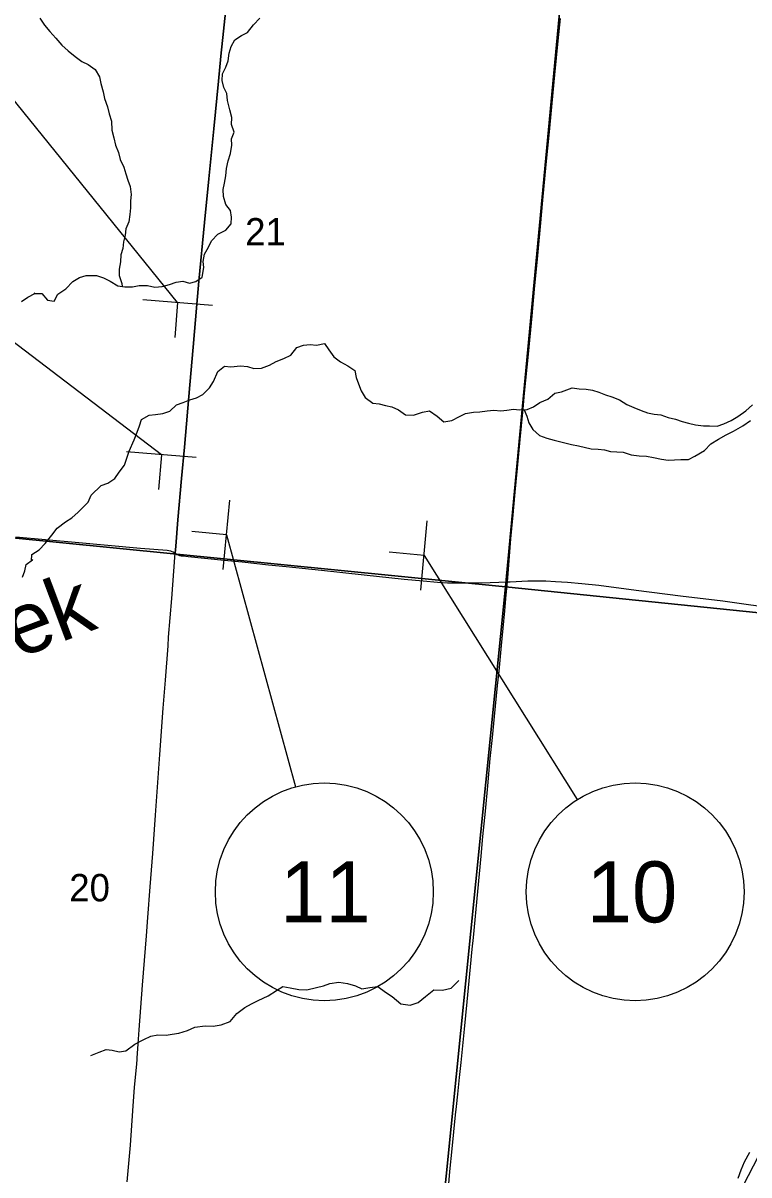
# Model space of a CAD drawing. Extents: x 0 to 1101, y 0 to 440.
# Drawn here: x 242.4 to 275.7, y 64.6 to 117.4 of the extents above; entities that cross this region are included whole.
import ezdxf

# ---------------------------------------------------------------- set-up
doc = ezdxf.new("R2010")
doc.units = 0
for name, color, linetype in [('Default', 7, 'Continuous'), ('GM_X_Minor_River', 7, 'Continuous'), ('GM_X_Minor_River_Text', 7, 'Continuous'), ('GM_X_Rail_Line', 7, 'Continuous'), ('GM_X_Section', 7, 'Continuous'), ('GM_X_Section_Text', 7, 'Continuous'), ('GM_X_State_Route', 7, 'Continuous'), ('GM_X_Township_Road', 7, 'Continuous'), ('GM_X_US_Route', 7, 'Continuous'), ('SH_Masking', 7, 'Continuous'), ('SH_Text', 7, 'Continuous'), ('SN_P_Signs', 7, 'Continuous')]:
    doc.layers.add(name, color=color, linetype=linetype)

msp = doc.modelspace()

# ---------------------------------------------------------------- linework, layer by layer
at = {"layer": 'Default'}
for points in [[(252.063, 121.444), (251.599, 117.072), (251.481, 115.922), (251.37, 114.772), (251.149, 112.584), (250.924, 110.283), (250.733, 108.279), (250.473, 105.589), (250.377, 104.531), (250.205, 102.562), (250.054, 100.835), (249.804, 97.976), (249.672, 96.528), (249.501, 94.634), (249.403, 93.416), (249.383, 93.096)], [(249.383, 93.096), (249.458, 93.046), (249.516, 93.02), (249.579, 93), (249.655, 92.986), (249.74, 92.977), (249.975, 92.954), (251.628, 92.788), (252.462, 92.697), (253.667, 92.571), (254.483, 92.487), (256.095, 92.315), (258.06, 92.112), (259.895, 91.912), (260.767, 91.826), (261.417, 91.766), (261.884, 91.743), (262.406, 91.734), (263.152, 91.736), (263.842, 91.753), (264.635, 91.788)], [(264.635, 91.788), (264.755, 91.793), (265.574, 91.828), (266.002, 91.833), (266.392, 91.827), (266.839, 91.809), (267.396, 91.772), (268.045, 91.713), (268.822, 91.626), (270.542, 91.411), (272.576, 91.151), (274.517, 90.907), (275.699, 90.747), (277.398, 90.516), (278.71, 90.338), (279.56, 90.23), (280.101, 90.164)]]:
    msp.add_lwpolyline(points, dxfattribs=at)
at = {"layer": 'GM_X_Minor_River'}
for points in [[(242.93, 105.021), (243.255, 105.021), (243.526, 104.722), (243.823, 104.673), (243.986, 104.992), (244.365, 105.24), (244.676, 105.568), (244.986, 105.76), (245.295, 105.848), (245.775, 105.855), (246.094, 105.749), (246.401, 105.587), (246.742, 105.378), (247.073, 105.329), (247.415, 105.326), (247.724, 105.391), (248.113, 105.388), (248.443, 105.316), (248.786, 105.347), (249.118, 105.435), (249.427, 105.547), (249.725, 105.59), (250.044, 105.495), (250.33, 105.573), (250.617, 105.776), (250.69, 106.209), (250.658, 106.496), (250.73, 106.826), (250.904, 107.156), (251.055, 107.441), (251.343, 107.746), (251.699, 107.926), (251.953, 108.221), (251.967, 108.529), (251.924, 108.827), (251.709, 109.115), (251.599, 109.481), (251.59, 109.801), (251.65, 110.086), (251.71, 110.429), (251.736, 110.76), (251.819, 111.113), (251.913, 111.444), (251.974, 111.832), (251.965, 112.118), (252.082, 112.436), (251.971, 112.78), (251.974, 113.1), (251.885, 113.455), (251.786, 113.879), (251.744, 114.199), (251.62, 114.486), (251.543, 114.795), (251.558, 115.103), (251.709, 115.41), (251.814, 115.706), (251.852, 116.049), (251.946, 116.368), (252.12, 116.675), (252.419, 116.866), (252.705, 117), (252.971, 117.363), (253.26, 117.658)], [(243.17, 117.661), (243.377, 117.339), (243.625, 117.051), (243.908, 116.751), (244.179, 116.417), (244.474, 116.163), (244.791, 115.909), (245.098, 115.678), (245.382, 115.538), (245.7, 115.307), (245.902, 114.962), (245.968, 114.664), (246.067, 114.275), (246.133, 113.977), (246.278, 113.599), (246.356, 113.278), (246.455, 112.935), (246.474, 112.523), (246.563, 112.168), (246.639, 111.825), (246.774, 111.492), (246.851, 111.171), (247.019, 110.815), (247.108, 110.517), (247.208, 110.219), (247.319, 109.933), (247.362, 109.567), (247.336, 109.27), (247.322, 108.95), (247.296, 108.653), (247.259, 108.31), (247.108, 107.992), (247.082, 107.695), (247, 107.387), (246.974, 107.09), (246.891, 106.794), (246.866, 106.474), (246.806, 106.143), (246.814, 105.846), (246.925, 105.479), (246.953, 105.347)], [(242.327, 104.651), (242.618, 104.859), (242.93, 105.021), (242.908, 105.045)], [(242.777, 92.752), (242.805, 93.043), (243.139, 93.258), (243.404, 93.552), (243.716, 93.927), (243.958, 94.256), (244.338, 94.539), (244.637, 94.73), (244.924, 94.979), (245.385, 95.444), (245.525, 95.762), (245.975, 96.204), (246.295, 96.316), (246.606, 96.53), (246.802, 96.814), (247.057, 97.143), (247.268, 97.782), (247.501, 98.305), (247.63, 98.659), (247.747, 98.943), (247.829, 99.24), (248.185, 99.431), (248.471, 99.462), (248.814, 99.517), (249.135, 99.628), (249.434, 99.911), (249.744, 100.022), (250.053, 100.145), (250.362, 100.234), (250.649, 100.391), (250.96, 100.686), (251.146, 100.981), (251.333, 101.437), (251.643, 101.685), (251.94, 101.66), (252.386, 101.701), (252.694, 101.664), (252.99, 101.581), (253.344, 101.601), (253.711, 101.735), (254.021, 101.903), (254.365, 102.037), (254.686, 102.194), (254.963, 102.546), (255.273, 102.657), (255.581, 102.677), (255.867, 102.652), (256.233, 102.728), (256.436, 102.429), (256.661, 102.119), (256.968, 101.887), (257.309, 101.701), (257.626, 101.481), (257.692, 101.171), (257.792, 100.873), (257.915, 100.552), (258.107, 100.253), (258.447, 99.987), (258.744, 99.95), (259.029, 99.878), (259.325, 99.819), (259.632, 99.678), (259.95, 99.447), (260.315, 99.432), (260.728, 99.577), (261.06, 99.642), (261.411, 99.399), (261.717, 99.133), (262.084, 99.198), (262.428, 99.378), (262.715, 99.512), (263.069, 99.578), (263.366, 99.586), (263.709, 99.629), (264.007, 99.66), (264.326, 99.634), (264.612, 99.666), (264.909, 99.709), (265.195, 99.683), (265.537, 99.692), (265.836, 99.815), (266.123, 100.018), (266.49, 100.174), (266.812, 100.446), (267.11, 100.511), (267.602, 100.69), (267.922, 100.641), (268.241, 100.626), (268.538, 100.578), (268.823, 100.495), (269.142, 100.378), (269.426, 100.284), (269.779, 100.143), (270.108, 99.934), (270.438, 99.783), (270.768, 99.654), (271.064, 99.548), (271.372, 99.488), (271.68, 99.451), (272.011, 99.333), (272.352, 99.25)], [(265.408, 99.689), (265.523, 99.395), (265.623, 99.085), (265.792, 98.775), (266.098, 98.497), (266.44, 98.38), (266.781, 98.285), (267.214, 98.178), (267.579, 98.095), (267.898, 98.023), (268.48, 97.892), (268.799, 97.877), (269.085, 97.852), (269.37, 97.769), (269.655, 97.755), (269.952, 97.741), (270.316, 97.623), (270.681, 97.574), (271.012, 97.559), (271.332, 97.488), (271.708, 97.416), (272.016, 97.367), (272.587, 97.396), (272.941, 97.404), (273.24, 97.561), (273.688, 97.82), (273.976, 98.114), (274.32, 98.328), (274.676, 98.542), (275.009, 98.699), (275.434, 98.947), (275.79, 99.195)], [(272.352, 99.25), (272.649, 99.144), (272.945, 99.073), (273.275, 98.99), (273.629, 98.941), (273.915, 98.95), (274.257, 98.935), (274.567, 99.046), (274.899, 99.192), (275.209, 99.383), (275.577, 99.631), (275.888, 99.914)], [(242.368, 91.995), (242.479, 92.289), (242.533, 92.584), (242.835, 92.792), (242.847, 92.826)], [(245.51, 70.039), (245.888, 70.193), (246.208, 70.314), (246.493, 70.287), (246.811, 70.215), (247.119, 70.256), (247.522, 70.558), (247.935, 70.78), (248.267, 70.935), (248.587, 70.988), (248.963, 70.983), (249.248, 71.025), (249.545, 71.066), (249.945, 71.186), (250.289, 71.341), (250.757, 71.403), (251.121, 71.387), (251.487, 71.45), (251.899, 71.604), (252.212, 71.964), (252.58, 72.244), (252.89, 72.411), (253.188, 72.567), (253.647, 72.788), (254.026, 73.022), (254.325, 73.212), (254.666, 73.15), (255.063, 73.065), (255.428, 73.06), (255.862, 73.168), (256.194, 73.244), (256.48, 73.342), (256.891, 73.405), (257.289, 73.354), (257.651, 73.235), (257.946, 73.106), (258.322, 73.158), (258.687, 73.21), (259.037, 72.954), (259.342, 72.756), (259.747, 72.42), (260.167, 72.346), (260.534, 72.478), (260.879, 72.758), (261.248, 73.05), (261.646, 73.044), (262.046, 73.13), (262.404, 73.478)], [(275.225, 64.404), (275.368, 64.801), (275.521, 65.163), (275.755, 65.604)]]:
    msp.add_lwpolyline(points, dxfattribs=at)
at = {"layer": 'GM_X_Rail_Line'}
msp.add_lwpolyline([(255.409, 27.207), (256.335, 28.435), (257.348, 30.06), (259.79, 33.772), (261.122, 36.152), (262.358, 38.564), (264.229, 42.213), (271.458, 56.334), (279.687, 72.261), (282.678, 78.347), (284.19, 81.266), (285.604, 83.513), (287.178, 85.826), (288.594, 87.771), (290.087, 89.842), (296.767, 97.839), (304.262, 106.782), (318.318, 123.252), (336.126, 144.564), (338.926, 147.955), (340.183, 149.461), (341.32, 151.069), (352.19, 166.043), (354.798, 169.6)], dxfattribs=at)
at = {"layer": 'GM_X_Section'}
for points in [[(267.417, 122.144), (264.55, 91.562), (233.896, 94.609), (236.891, 124.822)], [(267.417, 122.144), (299.077, 119.15), (295.742, 88.358), (264.55, 91.562)], [(233.896, 94.609), (264.55, 91.562), (261.598, 62.219), (231.008, 63.962)], [(295.742, 88.358), (292.555, 58.472), (261.598, 62.219), (264.55, 91.562)]]:
    msp.add_lwpolyline(points, close=True, dxfattribs=at)
at = {"layer": 'GM_X_State_Route'}
for points in [[(242.064, 93.845), (244.794, 93.609), (247.783, 93.336), (249.009, 93.233), (249.09, 93.222), (249.162, 93.208), (249.229, 93.185), (249.285, 93.156), (249.383, 93.096)], [(249.383, 93.096), (249.458, 93.046), (249.516, 93.02), (249.579, 93), (249.655, 92.986), (249.74, 92.977), (249.975, 92.954), (251.628, 92.788), (252.462, 92.697), (253.667, 92.571), (254.483, 92.487), (256.095, 92.315), (258.06, 92.112), (259.895, 91.912), (260.767, 91.826), (261.417, 91.766), (261.884, 91.743), (262.406, 91.734), (263.152, 91.736), (263.842, 91.753), (264.635, 91.788)], [(264.635, 91.788), (264.755, 91.793), (265.574, 91.828), (266.002, 91.833), (266.392, 91.827), (266.839, 91.809), (267.396, 91.772), (268.045, 91.713), (268.822, 91.626), (270.542, 91.411), (272.576, 91.151), (274.517, 90.907), (275.699, 90.747), (277.398, 90.516), (278.71, 90.338), (279.56, 90.23), (280.101, 90.164)]]:
    msp.add_lwpolyline(points, dxfattribs=at)
at = {"layer": 'GM_X_Township_Road'}
for points in [[(264.635, 91.788), (264.649, 91.971), (264.693, 92.565), (264.797, 93.754), (264.896, 94.868), (264.993, 95.907), (265.092, 97.002), (265.213, 98.32), (265.351, 99.73), (265.424, 100.454), (265.597, 102.234), (265.768, 103.996), (265.881, 105.221), (266.023, 106.762), (266.166, 108.265), (266.264, 109.304), (266.414, 110.937), (266.545, 112.292), (266.814, 115.056), (266.966, 116.614), (267.063, 117.653)], [(261.938, 64.155), (261.995, 64.717), (262.098, 65.756), (262.251, 67.315), (262.291, 67.704), (262.35, 68.26), (262.436, 69.038), (262.509, 69.724), (262.573, 70.335), (262.662, 71.244), (262.785, 72.506), (262.945, 74.12), (263.02, 74.918), (263.073, 75.456), (263.27, 77.571), (263.423, 79.186), (263.51, 80.095), (263.624, 81.256), (263.738, 82.414), (263.845, 83.677), (263.887, 84.092), (263.945, 84.645), (264.047, 85.605), (264.185, 87.034), (264.247, 87.683), (264.361, 88.87), (264.509, 90.448), (264.575, 91.186), (264.635, 91.788)]]:
    msp.add_lwpolyline(points, dxfattribs=at)
at = {"layer": 'GM_X_US_Route'}
for points in [[(249.383, 93.096), (249.403, 93.416), (249.501, 94.634), (249.672, 96.528), (249.804, 97.976), (250.054, 100.835), (250.205, 102.562), (250.377, 104.531), (250.473, 105.589), (250.733, 108.279), (250.924, 110.283), (251.149, 112.584), (251.37, 114.772), (251.481, 115.922), (251.599, 117.072), (252.063, 121.444)], [(247.183, 64.235), (247.323, 65.926), (247.435, 67.507), (247.518, 68.585), (247.616, 69.643), (247.613, 69.662), (247.631, 69.866), (247.633, 69.922), (247.68, 70.572), (247.726, 71.224), (247.884, 73.268), (248.057, 75.536), (248.126, 76.373), (248.239, 77.785), (248.354, 79.31), (248.478, 81.076), (248.679, 83.857), (248.832, 85.986), (248.939, 87.269), (249.054, 88.849), (249.078, 89.239), (249.22, 91.024), (249.363, 92.899), (249.383, 93.096)]]:
    msp.add_lwpolyline(points, dxfattribs=at)
at = {"layer": 'SH_Masking'}
for centre in [(256.227, 77.553), (270.499, 77.553)]:
    msp.add_circle(centre, 5, dxfattribs=at)
at = {"layer": 'SH_Text'}
for p, q in [((249.491, 104.603), (240.16, 116.129)), ((248.746, 97.623), (239.949, 104.326)), ((251.737, 93.948), (254.906, 82.376)), ((260.804, 92.994), (267.84, 81.788))]:
    msp.add_line(p, q, dxfattribs=at)
for centre in [(256.227, 77.553), (270.499, 77.553)]:
    msp.add_circle(centre, 5, dxfattribs=at)
at = {"layer": 'SN_P_Signs'}
for p, q in [((251.086, 104.473), (247.896, 104.732)), ((249.491, 104.603), (249.361, 103.008)), ((250.341, 97.493), (247.151, 97.752)), ((248.746, 97.623), (248.617, 96.028)), ((251.587, 92.355), (251.886, 95.541)), ((260.654, 91.401), (260.953, 94.587)), ((251.737, 93.948), (250.144, 94.098)), ((260.804, 92.994), (259.211, 93.143))]:
    msp.add_line(p, q, dxfattribs=at)

# ---------------------------------------------------------------- texts
at = {"layer": 'GM_X_Minor_River_Text'}
msp.add_text('Creek', height=2.8408, rotation=20.6145, dxfattribs=at).set_placement((236.405, 86.098))
at = {"layer": 'GM_X_Section_Text'}
for s, p in [('21', (252.593, 107.229)), ('20', (244.518, 77.119))]:
    msp.add_text(s, height=1.2557, rotation=0, dxfattribs=at).set_placement(p)
at = {"layer": 'SH_Text'}
for s, p in [('11', (254.193, 76.153)), ('10', (268.269, 76.153))]:
    msp.add_text(s, height=2.8, rotation=360, dxfattribs=at).set_placement(p)

doc.saveas('drawing.dxf')
